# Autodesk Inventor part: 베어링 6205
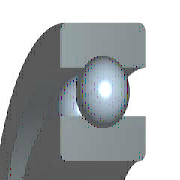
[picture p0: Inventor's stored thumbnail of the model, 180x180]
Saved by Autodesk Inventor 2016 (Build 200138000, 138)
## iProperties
Created: 2015-10
Part Number: 베어링 6205
Material: 강, 연강
Description: 깊은 그루브 볼 베어링
Document SubType Name: Modeling
Standard: KS B 2023
Designer: mdu
Standards Organization: KS
Language: ko-KR
Size Designation: 6205 - 25 x 52 x 15
Categories: <MemberInstance><Categories><Category DisplayName="샤프트 부품" InternalName="7f7aeb1f-a693-4053-b835-cee3144e0d98" Mnemonic="SHFT"><Category DisplayName="베어링" Inter
Density: 7.86 g/cm^3
Appearance: 노란색
Mass: 129.543 g
Surface Area: 107.326 cm^2
Volume: 16.4813 cm^3
IsCustomPart: 1
Author: mdu
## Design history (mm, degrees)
sketch "스케치" dims "d0" = 7.02 (= -0.26 x WD + 0.26 x BD)
  geometry: L1 (3.99, 19.25)-(11.01, 19.25); L2 (7.5, 19.25)-(7.5, 15.74); L3 (7.5, 19.25)-(7.5, 22.76); L4 (4.892, 16.901)-(0, 16.901); L5 (0, 12.5)-(15, 12.5); L6 (4.892, 21.599)-(0, 21.599); L7 (0, 26)-(15, 26); L8 (15, 12.5)-(15, 16.901); L9 (10.108, 16.901)-(15, 16.901); L10 (10.108, 21.599)-(15, 21.599); L11 (15, 26)-(15, 21.599); L12 (-1.4, 0)-(8.4, 0) reference; L13 (0, -0.3)-(0, 5.3) reference
  constraints: 22 end point, 4 point on line, 2 collinear, 2 perpendicular, 2 symmetric about line, 1 midpoint, 1 parallel, 14 other
  dimensions: "d9" = 25 diameter of L5 L12 (= WD); "d11" = 52 diameter of L7 L12 (= BD); "d12" = 15 distance between parallel lines of L8 L13 (= KB); "d13" = 33.802 diameter of L9 L12 (= 0.326 x BD + 0.674 x WD)
revolve "본체" stored, may be unused: angle "d6" = 90 deg
revolve "볼" stored, may be unused: angle "d7" = 90 deg
pattern_circular "IDS_ARRAYBALL[SIMPL:T]" dims angle "d3" = 360 deg
body "Solid1"
fillet "모깎기1" dims "d1" = 1 (= KRS)
other parameters: "WD" = 25 [user parameter; used in 5 equation terms], "BD" = 52 [user parameter; used in 5 equation terms], "KB" = 15 [user parameter; used in 1 equation term], "KRS" = 1 [user parameter; used in 1 equation term], "d4" = 0, "d5" = 0, "d8" = 0, "d14" = 0, "d15" = 0, "BBA" = 0 [user parameter], "BC0" = 7800000 [user parameter], "BC" = 1.4e+07 [user parameter], "BR" = 26 (= 0.5 x BD) [user parameter], "WR" = 12.5 (= 0.5 x WD) [user parameter]
